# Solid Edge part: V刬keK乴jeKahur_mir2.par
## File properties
Last saved by: Egon 815
Revision: 53
Accuracy: 0,990
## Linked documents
ljeKahur.par
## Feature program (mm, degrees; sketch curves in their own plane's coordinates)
part copy "CopiedPart_1"
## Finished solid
Body 1: solid body, 18 faces, 34 edges, 18 vertices.
  Faces by surface: plane 11, cone 3, cylinder 2, spline 2
  Edges by curve: line 14, circle 11, curve on surface 7, intersection 2
Bounding box of the edges (mm; curved faces can reach further): 2182.208 x 5485.690 x 2152.254, from (10802.6405, 23199.3222, 5032.5774) to (12984.8483, 28685.0118, 7184.8312).
Cylindrical faces by radius (mm): R125 x1, R1091.1039 x1
Conical faces (half-angle, radius in mm at the cone's reference point): 45 deg R1091.1039 x3
Planar faces by outward normal: +x 1, +y 4, +z 2, -x 1, -z 2, oblique 1
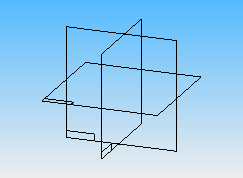
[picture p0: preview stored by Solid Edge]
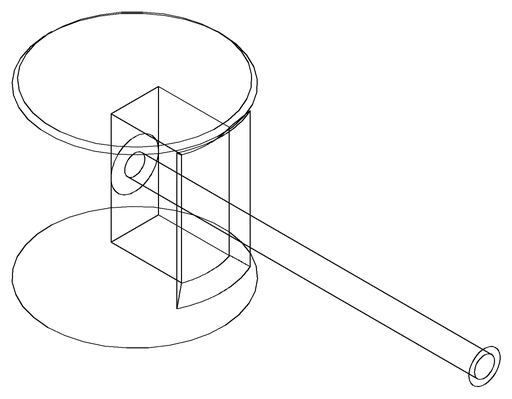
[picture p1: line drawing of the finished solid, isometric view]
